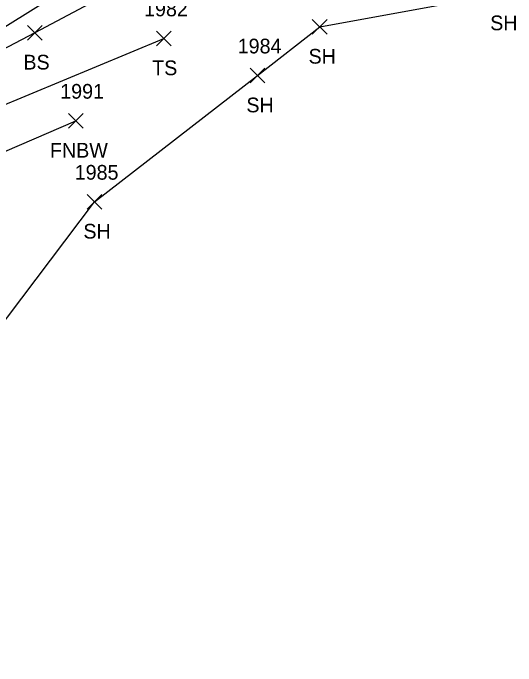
# Model space of a CAD drawing. Extents: x 1526508 to 1531550, y 369926 to 373082.
# Drawn here: x 1531334.3 to 1531402.5, y 370103.8 to 370192.4 of the extents above; entities that cross this region are included whole.
import ezdxf

# ---------------------------------------------------------------- set-up
doc = ezdxf.new("R2010")
doc.units = 0
for name, color, linetype in [('L_A', 7, 'Continuous'), ('L_I', 7, 'Continuous'), ('L_TIC', 7, 'Continuous'), ('LELB', 7, 'Continuous'), ('LFNC', 7, 'Continuous'), ('LSOGP', 7, 'Continuous')]:
    doc.layers.add(name, color=color, linetype=linetype)

msp = doc.modelspace()

# ---------------------------------------------------------------- linework, layer by layer
at = {"layer": 'L_TIC'}
for points in [[(1531374.891, 370189.567), (1531376.891, 370191.567)], [(1531376.891, 370189.567), (1531374.891, 370191.567)], [(1531336.217, 370188.771), (1531338.217, 370190.771)], [(1531338.217, 370188.771), (1531336.217, 370190.771)], [(1531353.731, 370187.998), (1531355.731, 370189.998)], [(1531355.731, 370187.998), (1531353.731, 370189.998)], [(1531366.448, 370182.957), (1531368.448, 370184.957)], [(1531368.448, 370182.957), (1531366.448, 370184.957)], [(1531341.782, 370176.809), (1531343.782, 370178.809)], [(1531343.782, 370176.809), (1531341.782, 370178.809)], [(1531344.313, 370165.81), (1531346.313, 370167.81)], [(1531346.313, 370165.81), (1531344.313, 370167.81)]]:
    msp.add_lwpolyline(points, dxfattribs=at)
at = {"layer": 'LELB'}
for points in [[(1531240.146, 370141.24), (1531255.535, 370153.738), (1531283.255, 370165.546), (1531305.03, 370178.456), (1531329.23, 370188.151), (1531348.159, 370200.006), (1531367.421, 370209.805)], [(1531369.651, 370204.019), (1531357.938, 370200.815), (1531337.217, 370189.771), (1531315.604, 370178.457), (1531299.037, 370171.081), (1531284.23, 370161.861), (1531268.987, 370153.567)], [(1531275.654, 370147.152), (1531300.945, 370167.048), (1531322.693, 370175.687), (1531354.731, 370188.998)]]:
    msp.add_lwpolyline(points, dxfattribs=at)
at = {"layer": 'LFNC'}
msp.add_lwpolyline([(1531276.585, 370145.243), (1531294.062, 370156.738), (1531311.984, 370165.178), (1531329.44, 370172.053), (1531342.782, 370177.809)], dxfattribs=at)
at = {"layer": 'LSOGP'}
msp.add_lwpolyline([(1531297.73, 370103.772), (1531345.313, 370166.81), (1531367.448, 370183.957), (1531375.891, 370190.567), (1531400.556, 370195.105)], dxfattribs=at)

# ---------------------------------------------------------------- texts
at = {"layer": 'L_A'}
for s, p in [('SH', (1531399.044, 370190.105)), ('SH', (1531374.38, 370185.567)), ('BS', (1531335.658, 370184.771)), ('TS', (1531353.141, 370183.998)), ('SH', (1531365.936, 370178.957)), ('FNBW', (1531339.255, 370172.809)), ('SH', (1531343.802, 370161.81))]:
    msp.add_text(s, height=2, dxfattribs=at).set_placement(p)
at = {"layer": 'L_I'}
for s, p in [('1982', (1531352.038, 370191.998)), ('1984', (1531364.755, 370186.957)), ('1991', (1531340.656, 370180.809)), ('1985', (1531342.621, 370169.81))]:
    msp.add_text(s, height=2, dxfattribs=at).set_placement(p)

doc.saveas('drawing.dxf')
